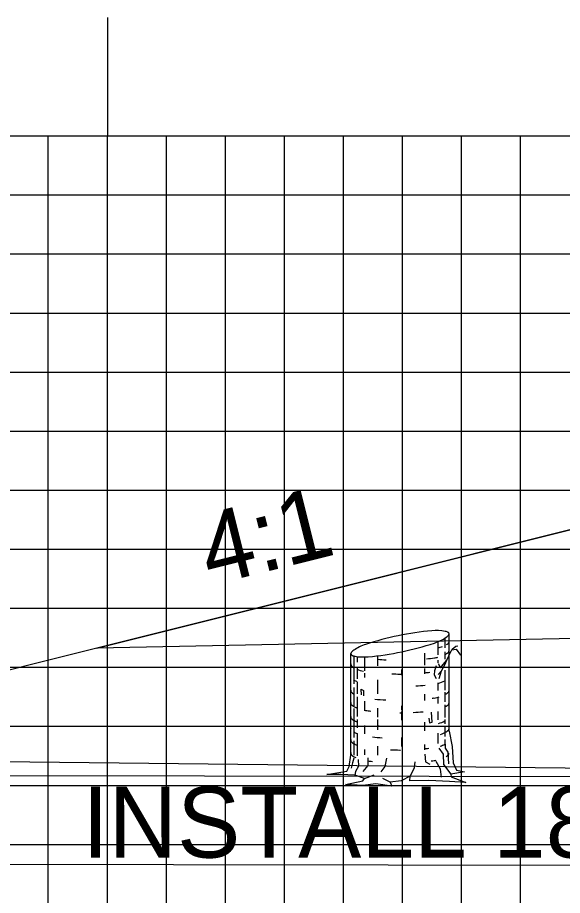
# Model space of a CAD drawing. Extents: x 1773203 to 1773546, y 442591 to 442811.
# Drawn here: x 1773337.11 to 1773346.34, y 442615.8 to 442630.67 of the extents above; entities that cross this region are included whole.
import ezdxf

# ---------------------------------------------------------------- set-up
doc = ezdxf.new("R2010")
doc.units = 0
for name, color, linetype in [('ANNOTATION', 7, 'Continuous'), ('D_Drainage_Culvert', 7, 'Continuous'), ('D_Drainage_Text', 7, 'Continuous'), ('D_Roadway_SlopeLines', 7, 'Continuous'), ('D_Roadway_SubGrade', 7, 'Continuous'), ('M_Trees_Conifer_Pay', 7, 'Continuous'), ('MAJOR', 7, 'Continuous'), ('MINOR', 7, 'Continuous'), ('S_Roadway_Centerline', 7, 'Continuous')]:
    doc.layers.add(name, color=color, linetype=linetype)

msp = doc.modelspace()

# ---------------------------------------------------------------- linework, layer by layer
at = {"layer": 'D_Drainage_Culvert'}
msp.add_lwpolyline([(1773328.842, 442617.84), (1773328.84, 442616.34), (1773408.84, 442616.22), (1773408.842, 442617.72)], close=True, dxfattribs=at)
at = {"layer": 'D_Roadway_SlopeLines'}
msp.add_lwpolyline([(1773348.634, 442622.534), (1773333.373, 442618.719)], dxfattribs=at)
at = {"layer": 'D_Roadway_SubGrade'}
msp.add_lwpolyline([(1773356.633, 442620.354), (1773338.457, 442619.99), (1773348.634, 442622.534), (1773348.633, 442622.284), (1773348.633, 442622.284), (1773356.633, 442622.604), (1773368.633, 442622.844), (1773380.633, 442622.604), (1773388.633, 442622.284), (1773388.633, 442622.284), (1773388.633, 442622.534), (1773398.809, 442619.99), (1773380.633, 442620.354), (1773368.633, 442620.594)], close=True, dxfattribs=at)
at = {"layer": 'M_Trees_Conifer_Pay'}
for p, q in [((1773344.423, 442618.584), (1773344.423, 442620.231)), ((1773344.234, 442620.098), (1773344.234, 442619.875)), ((1773344.351, 442620.159), (1773344.351, 442619.996)), ((1773344.351, 442619.928), (1773344.351, 442619.801)), ((1773342.759, 442618.174), (1773342.759, 442619.896)), ((1773342.806, 442619.858), (1773342.806, 442619.387)), ((1773342.864, 442619.847), (1773342.864, 442619.749)), ((1773342.989, 442619.839), (1773342.989, 442619.607)), ((1773343.209, 442619.86), (1773343.209, 442619.692)), ((1773344.005, 442619.902), (1773344.005, 442619.702)), ((1773344.234, 442619.786), (1773344.234, 442619.739)), ((1773342.864, 442619.675), (1773342.864, 442619.471)), ((1773344.005, 442619.644), (1773344.005, 442619.556)), ((1773342.989, 442619.566), (1773342.989, 442619.492)), ((1773343.615, 442619.628), (1773343.615, 442619.533)), ((1773344.291, 442619.603), (1773344.239, 442619.543)), ((1773344.351, 442619.614), (1773344.351, 442619.278)), ((1773342.864, 442619.413), (1773342.864, 442619.214)), ((1773343.209, 442619.455), (1773343.209, 442619.218)), ((1773344.234, 442619.404), (1773344.234, 442619.272)), ((1773342.806, 442619.323), (1773342.806, 442619.014)), ((1773344.005, 442619.208), (1773344.005, 442619.103)), ((1773344.351, 442619.241), (1773344.351, 442619.078)), ((1773342.864, 442619.167), (1773342.864, 442618.831)), ((1773342.989, 442619.089), (1773342.989, 442618.95)), ((1773344.234, 442619.161), (1773344.234, 442619.051)), ((1773342.806, 442618.967), (1773342.806, 442618.475)), ((1773343.209, 442618.973), (1773343.209, 442618.821)), ((1773343.615, 442619.014), (1773343.615, 442618.94)), ((1773343.615, 442618.915), (1773343.615, 442618.767)), ((1773344.234, 442618.915), (1773344.234, 442618.774)), ((1773344.351, 442619.031), (1773344.351, 442618.814)), ((1773342.864, 442618.778), (1773342.864, 442618.642)), ((1773343.209, 442618.778), (1773343.209, 442618.604)), ((1773344.351, 442618.783), (1773344.351, 442618.709)), ((1773342.989, 442618.678), (1773342.989, 442618.537)), ((1773344.005, 442618.736), (1773344.005, 442618.59)), ((1773344.351, 442618.669), (1773344.351, 442618.495)), ((1773342.864, 442618.543), (1773342.864, 442618.164)), ((1773343.615, 442618.475), (1773343.615, 442618.322)), ((1773344.234, 442618.547), (1773344.234, 442618.374)), ((1773342.806, 442618.421), (1773342.806, 442618.174)), ((1773343.209, 442618.327), (1773343.209, 442618.174)), ((1773344.005, 442618.358), (1773344.005, 442618.269)), ((1773342.989, 442618.275), (1773342.989, 442618.18)), ((1773342.989, 442617.781), (1773343.152, 442617.845)), ((1773343.426, 442617.717), (1773343.301, 442617.781))]:
    msp.add_line(p, q, dxfattribs=at)
for points in [[(1773344.239, 442619.729), (1773344.276, 442619.655), (1773344.323, 442619.712), (1773344.381, 442619.78), (1773344.474, 442619.974), (1773344.538, 442620.021), (1773344.569, 442620.028)], [(1773344.254, 442619.476), (1773344.291, 442619.603), (1773344.354, 442619.719), (1773344.385, 442619.786), (1773344.454, 442619.932)], [(1773344.468, 442619.962), (1773344.544, 442619.97), (1773344.616, 442619.871)], [(1773344.206, 442619.692), (1773344.175, 442619.607), (1773344.171, 442619.539), (1773344.202, 442619.476)], [(1773342.938, 442619.201), (1773342.932, 442619.297), (1773342.975, 442619.274), (1773342.975, 442619.179)], [(1773344.077, 442618.803), (1773344.089, 442618.726), (1773344.136, 442618.736), (1773344.124, 442618.903)], [(1773344.423, 442618.584), (1773344.474, 442618.322), (1773344.49, 442618.049), (1773344.548, 442617.923), (1773344.684, 442617.892), (1773344.453, 442617.855), (1773344.453, 442617.855), (1773344.459, 442617.808), (1773344.707, 442617.713), (1773344.432, 442617.73), (1773344.077, 442617.75), (1773343.755, 442617.74), (1773343.762, 442617.822), (1773343.613, 442617.74), (1773343.426, 442617.717), (1773343.451, 442617.649), (1773343.183, 442617.692), (1773342.963, 442617.665), (1773342.67, 442617.682), (1773342.959, 442617.74), (1773342.989, 442617.781), (1773342.827, 442617.839), (1773342.59, 442617.849), (1773342.349, 442617.849), (1773342.691, 442617.907), (1773342.732, 442617.987), (1773342.759, 442618.174)], [(1773344.348, 442618.442), (1773344.354, 442618.296), (1773344.402, 442618.228), (1773344.412, 442618.028)], [(1773344.249, 442618.296), (1773344.323, 442618.191), (1773344.328, 442618.018), (1773344.453, 442617.855)], [(1773344.012, 442618.191), (1773344.023, 442618.065), (1773344.097, 442618.022)], [(1773342.806, 442618.127), (1773342.785, 442618.049), (1773342.765, 442617.954)], [(1773342.884, 442618.106), (1773342.89, 442617.991), (1773342.837, 442617.902), (1773342.827, 442617.839)], [(1773343.047, 442618.133), (1773343.047, 442618.001), (1773342.959, 442617.902)], [(1773343.274, 442617.892), (1773343.341, 442617.987), (1773343.368, 442618.127)], [(1773343.762, 442617.822), (1773343.836, 442617.964), (1773343.846, 442618.065)], [(1773344.291, 442617.802), (1773344.276, 442617.94), (1773344.202, 442618.069)]]:
    msp.add_lwpolyline(points, dxfattribs=at)
for centre, radius, start, end in [((1773344.614, 442615.128), 5.179, 95.3794, 101.7194), ((1773344.204, 442619.486), 0.802, 79.2194, 95.3794), ((1773344.307, 442620.027), 0.251, 71.0501, 79.2194), ((1773344.362, 442620.187), 0.0817, 56.7194, 71.0501), ((1773344.378, 442620.211), 0.0527, 46.923, 56.7194), ((1773344.392, 442620.227), 0.0314, 34.2194, 46.923), ((1773344.397, 442620.23), 0.0264, 23.4074, 34.2194), ((1773344.391, 442620.232), 0.0314, 336.5158, 349.2194), ((1773344.4, 442620.231), 0.0226, 11.7194, 23.4074), ((1773344.4, 442620.231), 0.0226, 0.0315, 11.7194), ((1773344.396, 442620.231), 0.0264, 349.2194, 0.0315), ((1773344.614, 442615.128), 5.179, 101.7194, 108.0594), ((1773343.924, 442620.837), 0.802, 288.0594, 304.2194), ((1773344.234, 442620.381), 0.251, 304.2194, 312.3887), ((1773344.348, 442620.257), 0.0817, 312.3887, 326.7194), ((1773344.363, 442620.117), 0.0624, 311.2506, 330), ((1773344.372, 442620.241), 0.0527, 326.7194, 336.5158), ((1773344.379, 442620.108), 0.0441, 330, 343.9485), ((1773344.389, 442620.105), 0.0334, 343.9485, 354.2151), ((1773342.834, 442619.87), 0.0817, 132.3887, 146.7194), ((1773342.948, 442619.745), 0.251, 124.2194, 132.3887), ((1773343.257, 442619.29), 0.802, 108.0594, 124.2194), ((1773342.567, 442624.998), 5.179, 275.3794, 281.7194), ((1773342.567, 442624.998), 5.179, 281.7194, 288.0594), ((1773344.092, 442620.545), 0.571, 284.4317, 292.4132), ((1773344.291, 442620.199), 0.172, 300, 311.2506), ((1773344.363, 442619.962), 0.0624, 311.2506, 330), ((1773344.379, 442619.953), 0.0441, 330, 343.9485), ((1773344.389, 442619.95), 0.0334, 343.9485, 354.2151), ((1773342.79, 442619.894), 0.0314, 156.5158, 169.2194), ((1773342.785, 442619.895), 0.0264, 169.2194, 180.0315), ((1773342.781, 442619.895), 0.0226, 180.0315, 191.7194), ((1773342.781, 442619.895), 0.0226, 191.7194, 203.4074), ((1773342.785, 442619.897), 0.0264, 203.4074, 214.2194), ((1773342.81, 442619.886), 0.0527, 146.7194, 156.5158), ((1773342.789, 442619.9), 0.0314, 214.2194, 226.923), ((1773342.803, 442619.915), 0.0527, 226.923, 236.7194), ((1773342.819, 442619.94), 0.0817, 236.7194, 251.0501), ((1773342.874, 442620.099), 0.251, 251.0501, 259.2194), ((1773342.977, 442620.641), 0.802, 259.2194, 275.3794), ((1773343.591, 442623.908), 4.124, 264.6955, 266.7331), ((1773343.591, 442623.908), 4.124, 276.238, 278.1032), ((1773344.092, 442620.39), 0.571, 278.1032, 284.3667), ((1773344.092, 442620.39), 0.571, 297.0237, 300), ((1773344.291, 442620.045), 0.172, 300, 311.2506), ((1773342.791, 442619.717), 0.0334, 163.9485, 180), ((1773342.791, 442619.717), 0.0334, 180, 196.0515), ((1773342.801, 442619.72), 0.0441, 196.0515, 210), ((1773342.817, 442619.73), 0.0624, 210, 228.7494), ((1773342.889, 442619.812), 0.172, 228.7494, 240), ((1773343.089, 442620.157), 0.571, 240, 240.3367), ((1773343.089, 442620.157), 0.571, 246.8597, 257.9846), ((1773343.589, 442623.675), 4.124, 268.0751, 270), ((1773343.589, 442623.675), 4.124, 270, 270.3581), ((1773343.589, 442623.675), 4.124, 275.7849, 277.0558), ((1773344.389, 442619.506), 0.0334, 343.9485, 354.2151), ((1773343.09, 442619.946), 0.571, 240, 247.0587), ((1773343.591, 442623.464), 4.124, 273.7052, 275.9504), ((1773344.091, 442619.946), 0.571, 284.4493, 297.0429), ((1773342.791, 442619.271), 0.0334, 163.9485, 180), ((1773342.791, 442619.271), 0.0334, 180, 196.0515), ((1773342.801, 442619.274), 0.0441, 196.0515, 210), ((1773342.817, 442619.283), 0.0624, 210, 228.7494), ((1773342.889, 442619.365), 0.172, 228.7494, 240), ((1773343.089, 442619.71), 0.571, 240, 240.3367), ((1773344.09, 442619.71), 0.571, 297.1896, 300), ((1773344.289, 442619.365), 0.172, 300, 311.2506), ((1773344.362, 442619.283), 0.0624, 311.2506, 330), ((1773344.378, 442619.274), 0.0441, 330, 343.9485), ((1773344.388, 442619.271), 0.0334, 343.9485, 354.2151), ((1773342.791, 442619.061), 0.0334, 163.9485, 180), ((1773342.791, 442619.061), 0.0334, 180, 196.0515), ((1773342.801, 442619.064), 0.0441, 196.0515, 210), ((1773342.817, 442619.073), 0.0624, 210, 228.7494), ((1773343.589, 442623.228), 4.124, 264.081, 266.6676), ((1773343.589, 442623.228), 4.124, 277.6125, 278.1032), ((1773344.09, 442619.71), 0.571, 278.1032, 286.9296), ((1773344.362, 442619.073), 0.0624, 311.2506, 330), ((1773344.378, 442619.064), 0.0441, 330, 343.9485), ((1773344.388, 442619.061), 0.0334, 343.9485, 354.2151), ((1773342.889, 442619.155), 0.172, 228.7494, 240), ((1773343.089, 442619.5), 0.571, 240, 246.8597), ((1773343.089, 442619.5), 0.571, 259.2707, 261.8968), ((1773343.589, 442623.018), 4.124, 261.8968, 263.1474), ((1773343.589, 442623.018), 4.124, 270, 270.3581), ((1773343.589, 442623.018), 4.124, 273.1493, 275.4569), ((1773344.09, 442619.5), 0.571, 297.1896, 300), ((1773344.289, 442619.155), 0.172, 300, 311.2506), ((1773342.791, 442618.824), 0.0334, 163.9485, 180), ((1773342.791, 442618.824), 0.0334, 180, 196.0515), ((1773342.801, 442618.827), 0.0441, 196.0515, 210), ((1773342.817, 442618.836), 0.0624, 210, 228.7494), ((1773342.889, 442618.919), 0.172, 228.7494, 240), ((1773343.089, 442619.264), 0.571, 240, 246.8597), ((1773344.09, 442619.264), 0.571, 285.3983, 297.1896), ((1773342.791, 442618.626), 0.0334, 163.9485, 180), ((1773343.589, 442622.781), 4.124, 264.716, 266.3193), ((1773344.289, 442618.721), 0.172, 300, 311.2506), ((1773344.362, 442618.638), 0.0624, 311.2506, 330), ((1773344.378, 442618.629), 0.0441, 330, 343.9485), ((1773344.388, 442618.626), 0.0334, 343.9485, 354.2151), ((1773343.078, 442619.072), 0.571, 241.2369, 248.0268), ((1773343.589, 442622.583), 4.124, 263.4991, 265.8397), ((1773344.09, 442619.066), 0.571, 289.2907, 300), ((1773342.791, 442618.431), 0.0334, 163.9485, 180), ((1773342.791, 442618.431), 0.0334, 180, 196.0515), ((1773342.801, 442618.434), 0.0441, 196.0515, 210), ((1773342.817, 442618.443), 0.0624, 210, 228.7494), ((1773342.889, 442618.525), 0.172, 228.7494, 240), ((1773343.089, 442618.87), 0.571, 240, 246.8597), ((1773343.589, 442622.388), 4.124, 275.7849, 276.7896), ((1773344.09, 442618.87), 0.571, 288.5067, 297.2721), ((1773342.791, 442618.21), 0.0334, 163.9485, 180), ((1773342.791, 442618.21), 0.0334, 180, 196.0515), ((1773342.801, 442618.213), 0.0441, 196.0515, 210), ((1773342.817, 442618.222), 0.0624, 210, 228.7494), ((1773342.889, 442618.305), 0.172, 228.7494, 240), ((1773343.089, 442618.65), 0.571, 240, 244.5314), ((1773343.589, 442622.388), 4.124, 267.8117, 270), ((1773343.589, 442622.388), 4.124, 270, 270.1328), ((1773344.289, 442618.305), 0.172, 300, 311.2506), ((1773344.362, 442618.222), 0.0624, 311.2506, 330), ((1773344.378, 442618.213), 0.0441, 330, 343.9485), ((1773344.388, 442618.21), 0.0334, 343.9485, 354.2151), ((1773343.589, 442622.168), 4.124, 262.4438, 263.512), ((1773343.589, 442622.168), 4.124, 277.3684, 278.1032), ((1773344.09, 442618.65), 0.571, 278.1032, 281.637)]:
    msp.add_arc(centre, radius, start, end, dxfattribs=at)
at = {"layer": 'MAJOR'}
for p, q in [((1773338.633, 442630.669), (1773338.633, 442628.665)), ((1773228.633, 442628.665), (1773508.633, 442628.665)), ((1773228.633, 442628.665), (1773508.633, 442628.665)), ((1773338.633, 442608.665), (1773338.633, 442628.665)), ((1773228.633, 442623.665), (1773508.633, 442623.665)), ((1773228.633, 442618.665), (1773508.633, 442618.665))]:
    msp.add_line(p, q, dxfattribs=at)
at = {"layer": 'MINOR'}
for p, q in [((1773337.633, 442608.665), (1773337.633, 442628.665)), ((1773339.633, 442608.665), (1773339.633, 442628.665)), ((1773340.633, 442608.665), (1773340.633, 442628.665)), ((1773341.633, 442608.665), (1773341.633, 442628.665)), ((1773342.633, 442608.665), (1773342.633, 442628.665)), ((1773343.633, 442608.665), (1773343.633, 442628.665)), ((1773344.633, 442608.665), (1773344.633, 442628.665)), ((1773345.633, 442608.665), (1773345.633, 442628.665)), ((1773228.633, 442627.665), (1773508.633, 442627.665)), ((1773228.633, 442626.665), (1773508.633, 442626.665)), ((1773228.633, 442625.665), (1773508.633, 442625.665)), ((1773228.633, 442624.665), (1773508.633, 442624.665)), ((1773228.633, 442622.665), (1773508.633, 442622.665)), ((1773228.633, 442621.665), (1773508.633, 442621.665)), ((1773228.633, 442620.665), (1773508.633, 442620.665)), ((1773228.633, 442619.665), (1773508.633, 442619.665)), ((1773228.633, 442617.665), (1773508.633, 442617.665)), ((1773228.633, 442616.665), (1773508.633, 442616.665))]:
    msp.add_line(p, q, dxfattribs=at)
at = {"layer": 'S_Roadway_Centerline'}
msp.add_lwpolyline([(1773304.246, 442619.123), (1773316.056, 442618.769), (1773325.791, 442618.283), (1773327.822, 442618.218), (1773329.759, 442618.149), (1773347.396, 442617.953), (1773350.966, 442617.999), (1773356.015, 442617.783), (1773363.1, 442617.486), (1773368.852, 442617.324), (1773375.69, 442617.133), (1773386.091, 442616.801), (1773391.839, 442616.688), (1773407.669, 442616.423), (1773417.972, 442616.208), (1773429.278, 442615.936)], dxfattribs=at)

# ---------------------------------------------------------------- texts
at = {"layer": 'ANNOTATION'}
msp.add_text('4:1', height=1.2, rotation=14.0411, dxfattribs=at).set_placement((1773340.371, 442621.044))
at = {"layer": 'D_Drainage_Text'}
msp.add_text('INSTALL 18" X 80\' RCP CLASS III', height=1.2, dxfattribs=at).set_placement((1773338.21, 442616.441))

doc.saveas('drawing.dxf')
